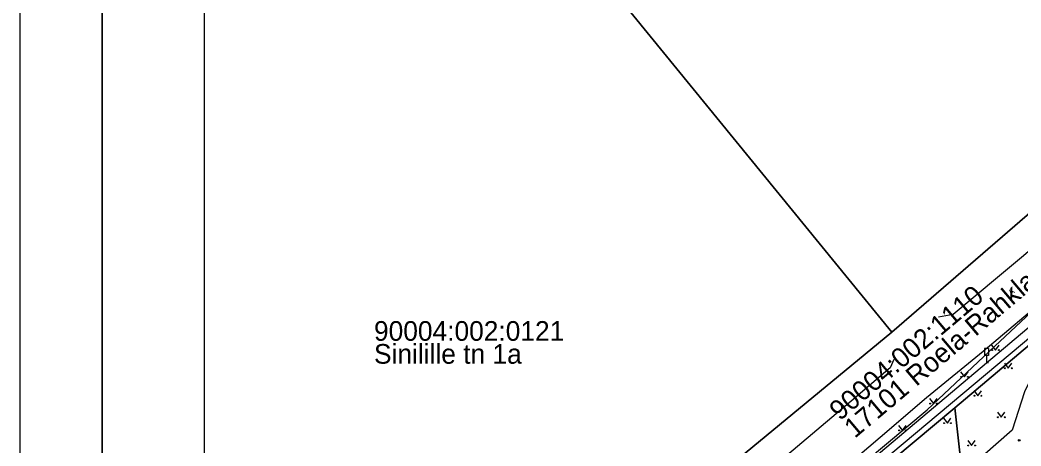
# Model space of a CAD drawing. Extents: x 648017 to 648227, y 6561313 to 6561610.
# Drawn here: x 648016.8 to 648138.8, y 6561458.6 to 6561510.6 of the extents above; entities that cross this region are included whole.
import ezdxf

# ---------------------------------------------------------------- set-up
doc = ezdxf.new("R2010")
doc.units = 0
for name, color, linetype in [('HALJASTUS', 7, 'Continuous'), ('KASUTUSALA', 7, 'Continuous'), ('LIIKLUS', 7, 'Continuous'), ('PIIR', 7, 'Continuous'), ('PR_SIDE', 7, 'Continuous'), ('SITRASS', 7, 'Continuous'), ('TEE', 7, 'Continuous'), ('VORMISTUS', 7, 'Continuous')]:
    doc.layers.add(name, color=color, linetype=linetype)

msp = doc.modelspace()

# ---------------------------------------------------------------- linework, layer by layer
at = {"layer": 'HALJASTUS'}
for p, q in [((648135.25, 6561470.97), (648135.72, 6561470.36)), ((648135.72, 6561470.36), (648136.16, 6561470.97)), ((648131.47, 6561467.7), (648131.94, 6561467.09)), ((648131.94, 6561467.09), (648132.38, 6561467.7)), ((648136.82, 6561468.74), (648137.28, 6561468.13)), ((648137.28, 6561468.13), (648137.73, 6561468.74)), ((648133.11, 6561465.39), (648133.57, 6561464.78)), ((648133.57, 6561464.78), (648134.02, 6561465.39)), ((648127.69, 6561464.43), (648128.16, 6561463.82)), ((648128.16, 6561463.82), (648128.6, 6561464.43)), ((648129.39, 6561462.04), (648129.86, 6561461.43)), ((648129.86, 6561461.43), (648130.3, 6561462.04)), ((648135.96, 6561462.77), (648136.42, 6561462.16)), ((648136.42, 6561462.16), (648136.87, 6561462.77)), ((648123.91, 6561461.15), (648124.38, 6561460.55)), ((648124.38, 6561460.55), (648124.82, 6561461.15)), ((648132.34, 6561459.32), (648132.81, 6561458.71)), ((648132.81, 6561458.71), (648133.25, 6561459.32))]:
    msp.add_line(p, q, dxfattribs=at)
msp.add_lwpolyline([(648185.62, 6561501.03), (648186.16, 6561502.54), (648178.05, 6561502.67), (648168.97, 6561497.05), (648166.52, 6561494.37), (648160.96, 6561490.07), (648158.7, 6561487.31), (648156.13, 6561485.11), (648153.03, 6561483.54), (648142.94, 6561474.36), (648140.84, 6561468.51), (648139.27, 6561465.25), (648137.74, 6561460.57), (648130.77, 6561454.44), (648126.4, 6561456.4), (648120.99, 6561455.34), (648118.74, 6561454.03), (648113.28, 6561447.47), (648113.2, 6561446.44), (648114.77, 6561444.87), (648116.61, 6561441.07)], dxfattribs=at)
for centre, radius in [((648135.32, 6561470.36), 0.055), ((648136.15, 6561470.36), 0.055), ((648136.88, 6561468.13), 0.055), ((648137.71, 6561468.13), 0.055), ((648131.54, 6561467.09), 0.055), ((648132.37, 6561467.09), 0.055), ((648133.17, 6561464.78), 0.055), ((648134, 6561464.78), 0.055), ((648127.76, 6561463.82), 0.055), ((648128.59, 6561463.82), 0.055), ((648136.02, 6561462.16), 0.055), ((648136.85, 6561462.16), 0.055), ((648123.98, 6561460.55), 0.055), ((648124.81, 6561460.55), 0.055), ((648129.46, 6561461.43), 0.055), ((648130.29, 6561461.43), 0.055), ((648138.62, 6561459.34), 0.1), ((648132.4, 6561458.71), 0.055), ((648133.23, 6561458.71), 0.055)]:
    msp.add_circle(centre, radius, dxfattribs=at)
at = {"layer": 'KASUTUSALA'}
msp.add_lwpolyline([(648069.33, 6561411.95), (648079.41, 6561420.36), (648130.76, 6561463.29), (648148.46, 6561478.24), (648152.69, 6561481.86), (648163.17, 6561490.84), (648165.15, 6561492.84), (648178.34, 6561506.54), (648179.79, 6561507.81), (648180.15, 6561508.27), (648181.07, 6561509.57), (648179.72, 6561510.41), (648176.96, 6561507.99), (648163.75, 6561494.27), (648163.1, 6561493.67), (648154.2, 6561485.9), (648141.11, 6561474.19), (648118.07, 6561454.82), (648078.72, 6561421.74), (648068.5, 6561412.94), (648066.26, 6561409.59)], close=True, dxfattribs=at)
at = {"layer": 'LIIKLUS'}
for p, q in [((648134.39, 6561470.53), (648134.39, 6561469.68)), ((648134.89, 6561470.53), (648134.39, 6561470.53)), ((648134.89, 6561470.53), (648134.89, 6561469.68)), ((648134.89, 6561469.68), (648134.39, 6561469.68)), ((648134.64, 6561469.68), (648134.64, 6561468.78)), ((648134.89, 6561468.78), (648134.64, 6561468.78))]:
    msp.add_line(p, q, dxfattribs=at)
at = {"layer": 'PIIR'}
for points in [[(648199.34, 6561559.88), (648199.07, 6561558.2), (648195.16, 6561543.45), (648190.37, 6561530.46), (648184.89, 6561519.28), (648179.37, 6561510.62), (648181.07, 6561509.57), (648180.15, 6561508.27), (648175.42, 6561502.2), (648170.88, 6561497.65), (648163.17, 6561490.84), (648148.46, 6561478.24), (648130.76, 6561463.29), (648079.41, 6561420.36), (648069.33, 6561411.95), (648039.27, 6561388.87)], [(648148.78, 6561559.88), (648090, 6561513.15), (648123.09, 6561472.56), (648039.27, 6561403.33)], [(648039.27, 6561403.33), (648123.09, 6561472.56), (648162.4, 6561506.57), (648170.84, 6561515.84), (648172.53, 6561514.72), (648177.65, 6561522.71), (648182.83, 6561533.2), (648187.47, 6561545.71), (648191.21, 6561559.62), (648191.24, 6561559.88)], [(648191.24, 6561559.88), (648191.21, 6561559.62), (648187.47, 6561545.71), (648182.83, 6561533.2), (648177.65, 6561522.71), (648172.53, 6561514.72), (648170.84, 6561515.84), (648162.4, 6561506.57), (648123.09, 6561472.56), (648090, 6561513.15), (648148.78, 6561559.88)], [(648128.28, 6561349.88), (648122.86, 6561391.28), (648138.52, 6561393.32), (648130.76, 6561463.29), (648148.46, 6561478.24), (648163.17, 6561490.84), (648170.88, 6561497.65), (648175.42, 6561502.2), (648180.15, 6561508.27), (648181.07, 6561509.57), (648185.28, 6561507.91), (648190.43, 6561507.33), (648190.49, 6561494.61), (648191.59, 6561478.79), (648183.88, 6561478.99), (648183.75, 6561472.33), (648192.14, 6561472), (648192.72, 6561465.96), (648194.12, 6561456.75), (648195.36, 6561449.36), (648197.34, 6561442.54), (648200.74, 6561433.7), (648204.28, 6561426.35)]]:
    msp.add_lwpolyline(points, dxfattribs=at)
msp.add_lwpolyline([(648079.41, 6561420.36), (648130.76, 6561463.29), (648138.52, 6561393.32), (648122.86, 6561391.28), (648085.73, 6561386.66)], close=True, dxfattribs=at)
at = {"layer": 'PR_SIDE'}
msp.add_lwpolyline([(648199.29, 6561518.48), (648197.48, 6561519.53), (648193.72, 6561520.51), (648192, 6561519.84), (648177.65, 6561507.26), (648164.45, 6561493.55), (648163.77, 6561492.92), (648154.87, 6561485.15), (648141.77, 6561473.44), (648118.71, 6561454.06), (648079.38, 6561420.99), (648069.19, 6561412.21), (648060.53, 6561403.42), (648044.66, 6561390.62), (648039.27, 6561386.53)], dxfattribs=at)
at = {"layer": 'SITRASS'}
msp.add_lwpolyline([(648102.92, 6561428.85), (648102.88, 6561429.06), (648103.27, 6561433.88), (648104.47, 6561437.15), (648105.93, 6561440.13), (648107.48, 6561443.06), (648108.63, 6561445.32), (648111.07, 6561448.46), (648115.64, 6561452.59), (648119.94, 6561456.82), (648127.38, 6561463.08), (648135.65, 6561470.85), (648142, 6561476.76)], dxfattribs=at)
at = {"layer": 'TEE'}
for points in [[(648180.64, 6561526.05), (648175.16, 6561516.61), (648168.19, 6561507.6), (648157.52, 6561497.62), (648149.94, 6561491.11), (648138.91, 6561481.66), (648130.58, 6561474.7), (648128.76, 6561474.38)], [(648190.85, 6561503.01), (648190.8, 6561505.33), (648190.47, 6561508.69), (648186.91, 6561508.39), (648184.05, 6561507.67), (648178.23, 6561505.8), (648172.6, 6561503.64), (648169.6, 6561500.66), (648161.13, 6561493.28), (648153.24, 6561486.39), (648142.3, 6561477.02), (648134.21, 6561470.18), (648127.3, 6561464.53), (648121.65, 6561459.67), (648108.95, 6561448.83), (648091.71, 6561434.54), (648078.47, 6561423.42), (648076.86, 6561419.22), (648076.8, 6561415.34), (648077.81, 6561412.28), (648079.89, 6561408.03), (648080.81, 6561407.12)], [(648123.33, 6561469.2), (648122.88, 6561468.2), (648118.14, 6561464.11), (648105.57, 6561453.51), (648088.28, 6561439.26), (648074.86, 6561428.43), (648059.76, 6561415.88), (648040.75, 6561400.23), (648039.27, 6561399.14)]]:
    msp.add_lwpolyline(points, dxfattribs=at)
at = {"layer": 'VORMISTUS'}
for points in [[(648016.78, 6561609.88), (648226.78, 6561609.88), (648226.78, 6561312.88), (648016.78, 6561312.88)], [(648026.78, 6561323.88), (648216.78, 6561323.88), (648216.78, 6561598.88), (648026.78, 6561598.88)], [(648026.78, 6561598.88), (648216.78, 6561598.88), (648216.78, 6561323.88), (648026.78, 6561323.88)], [(648204.28, 6561349.88), (648039.27, 6561349.88), (648039.27, 6561559.88), (648204.28, 6561559.88)]]:
    msp.add_lwpolyline(points, close=True, dxfattribs=at)

# ---------------------------------------------------------------- texts
at = {"layer": 'PIIR'}
for s, p in [('17101 Roela-Rahkla tee', (648118.56, 6561459.51)), ('90004:002:1110', (648116.75, 6561461.65))]:
    msp.add_text(s, height=2.4, rotation=40.1668, dxfattribs=at).set_placement(p)
for s, p in [('90004:002:0121', (648059.94, 6561471.49)), ('Sinilille tn 1a', (648059.94, 6561468.69))]:
    msp.add_text(s, height=2.4, dxfattribs=at).set_placement(p)
at = {"layer": 'TEE'}
msp.add_text('A', height=0.7, rotation=42.4084, dxfattribs=at).set_placement((648137.67, 6561476.98))

doc.saveas('drawing.dxf')
